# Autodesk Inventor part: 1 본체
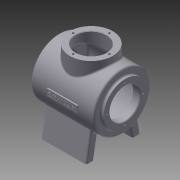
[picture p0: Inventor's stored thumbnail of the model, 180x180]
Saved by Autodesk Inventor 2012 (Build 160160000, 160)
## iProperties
Created: 2015-01
Part Number: 1 본체
Material: 알루미늄-6061
Document SubType Name: Modeling
Designer: Owner
Mass: 1021.13 g
Surface Area: 1060.1 cm^2
Volume: 376.801 cm^3
Density: 2.71 g/cm^3
Author: Owner
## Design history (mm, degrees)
sketch "스케치1"
  geometry: L1 (-61, 0)-(61, 0); L2 (-50, 27)-(-50, 45); L3 (-50, 45)-(47, 45); L4 (47, 45)-(47, 27); L5 (47, 27)-(60, 27); L6 (60, 27)-(60, 38); L7 (60, 38)-(55, 38); L8 (55, 38)-(55, 50); L9 (55, 50)-(-57, 50); L10 (-57, 50)-(-57, 38); L11 (-57, 38)-(-62, 38); L12 (-62, 38)-(-62, 27); L13 (-50, 27)-(-62, 27); 2 further points
  constraints: 26 end point, 5 parallel, 1 coincident, 1 horizontal, 1 horizontal alignment, 1 midpoint, 1 perpendicular
  dimensions: "d0" = 122 distance of L1.start L1.end; "d2" = 90 diameter of L3 L1; "d3" = 54 diameter of L5 L1; "d4" = 76 diameter of L6.end L1; "d5" = 100 diameter of L9 L1; "d6" = 112 distance of L8.end L9.end; "d7" = 60 horizontal distance of L6.end point (0, 0); "d9" = 5 distance of L6.end L7.end; "d75" = 13 distance between parallel lines of L4 L6; "d76" = 97 distance of L2.end L3.end; "d77" = 76 diameter of L11 L1; "d78" = 62 distance from line of L12 point (0, 0); "d79" = 54 diameter of L13 L1
revolve "회전1" sketch "스케치1" stored, may be unused: angle "d11" = 90 deg
node "작업 평면2"
  node "작업 평면1"
sketch "스케치2"
  geometry: C1 r 38 at (-1, 0); 1 further point
  constraints: 1 centre point, 1 coincident
  dimensions: "d13" = 76 diameter of C1
extrude "돌출1" join sketch "스케치2" stored distance "d14" = 10; taper "d15" = 0 deg
sketch "스케치3"
  geometry: C1 r 38 at (0, 0) reference; C2 r 27 at (0, 0)
  constraints: 1 centre point, 1 coincident
  dimensions: "d16" = 54 diameter of C2
extrude "돌출2" cut sketch "스케치3" stored distance "d17" = 10; taper "d18" = 0 deg
sketch "스케치4" dims "d19" = 64
  geometry: C1 r 27 at (0, 0) reference; C2 r 38 at (0, 0) reference; 2 further points
  constraints: 2 vertical alignment, 1 coincident, 2 other
hole "구멍1" sketch "스케치4" at (0, 32) diameter "d20" = 3.242; stored, may be unused: countersink angle "d24" = 90 deg, drill point angle "d26" = 118 deg; dims "d21" = 8, "d22" = 4, "d23" = 2, "d25" = 10
sketch "스케치5" dims "d30" = 64
  geometry: C1 r 27 at (0, 0) reference; C2 r 38 at (0, 0) reference; 2 further points
  constraints: 2 vertical alignment, 1 coincident, 2 other
hole "구멍2" sketch "스케치5" at (0, 32) diameter "d31" = 3.242; stored, may be unused: countersink angle "d35" = 90 deg, drill point angle "d37" = 118 deg; dims "d32" = 8, "d33" = 4, "d34" = 2, "d36" = 10
sketch "스케치6" dims "d41" = 64
  geometry: C1 r 38 at (0, 0) reference; C2 r 27 at (0, 0) reference; 2 further points
  constraints: 2 vertical alignment, 1 coincident, 2 other
hole "구멍3" sketch "스케치6" at (0, 32) diameter "d42" = 3.242; stored, may be unused: countersink angle "d46" = 90 deg, drill point angle "d48" = 118 deg; dims "d43" = 8, "d44" = 4, "d45" = 2, "d47" = 10
node "작업 평면3"
sketch "스케치7"
  geometry: L1 (-39.336, -30.865)-(-48, -80); L2 (-48, -80)-(-34, -80); L3 (-34, -80)-(-27.282, -41.901); A1 r 50 centre (0, 0) between (-39.336, -30.865) and (-27.282, -41.901) reference; 1 further point
  constraints: 6 end point, 2 point on circle, 1 horizontal, 1 parallel
  dimensions: "d53" = 100 deg angle of L2 L1; "d54" = 14 distance of L1.end L2.end; "d55" = 80 distance from line of L2 point (0, 0); "d56" = 48 horizontal distance of point (0, 0) L1.end
extrude "돌출3" join sketch "스케치7" stored distance "d57" = 80; taper "d58" = 0 deg
node "작업 평면6"
  node "작업 평면5"
sketch "스케치9"
  geometry: L1 (-26, 6)-(28, 6); L2 (28, 6)-(28, -6); L3 (28, -6)-(-26, -6); L4 (-26, -6)-(-26, 6); L5 (28, -6)-(-26, 6); 2 further points
  constraints: 10 end point, 2 parallel, 1 coincident, 1 horizontal, 1 midpoint, 1 perpendicular
  dimensions: "d63" = 54 distance of L2.end L3.end; "d64" = 12 distance of L1.end L2.end
extrude "돌출4" join sketch "스케치9" stored distance "d65" = 80; taper "d66" = 0 deg
node "작업 평면7"
sketch "스케치10"
  geometry: 2 further points
  constraints: 1 coincident, 1 other
feature "엠보싱1" sketch "스케치10" dims "d68" = 0.5, "d69" = 0
chamfer "모따기1" distance "d70" = 1; stored, may be unused: second distance "d71" = 2, angle "d72" = 45 deg
fillet "모깎기1" dims "d73" = 3
fillet "모깎기2" dims "d74" = 3
node "솔리드1"
pattern_circular "원형 패턴1" dims angle "d28" = 360 deg
pattern_circular "원형 패턴2" dims angle "d39" = 360 deg
pattern_circular "원형 패턴3" dims angle "d50" = 360 deg
mirror "대칭1"
other parameters: "d12" = 12, "d52" = -61, "d62" = 2
